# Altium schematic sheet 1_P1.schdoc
size 431 x 309 mm; Symbol: Sheet-Symbol_A3; Device: Sheet-Symbol_A3; Company: PCBCrew.com; Drawed: DumTux; Reviewed: EasyEDA Pro; Version: V0.1; Page Size: A3; @Project Name: BLDGOT ESP32 Temperature Controller; @Page Count: 2; @Update Date: 2023-02-26; @Create Date: 2023-02-25; @Schematic Name: Temperature Controller; Part Number: JLCPCB-001; @Page No: 1; @Page Name: P1
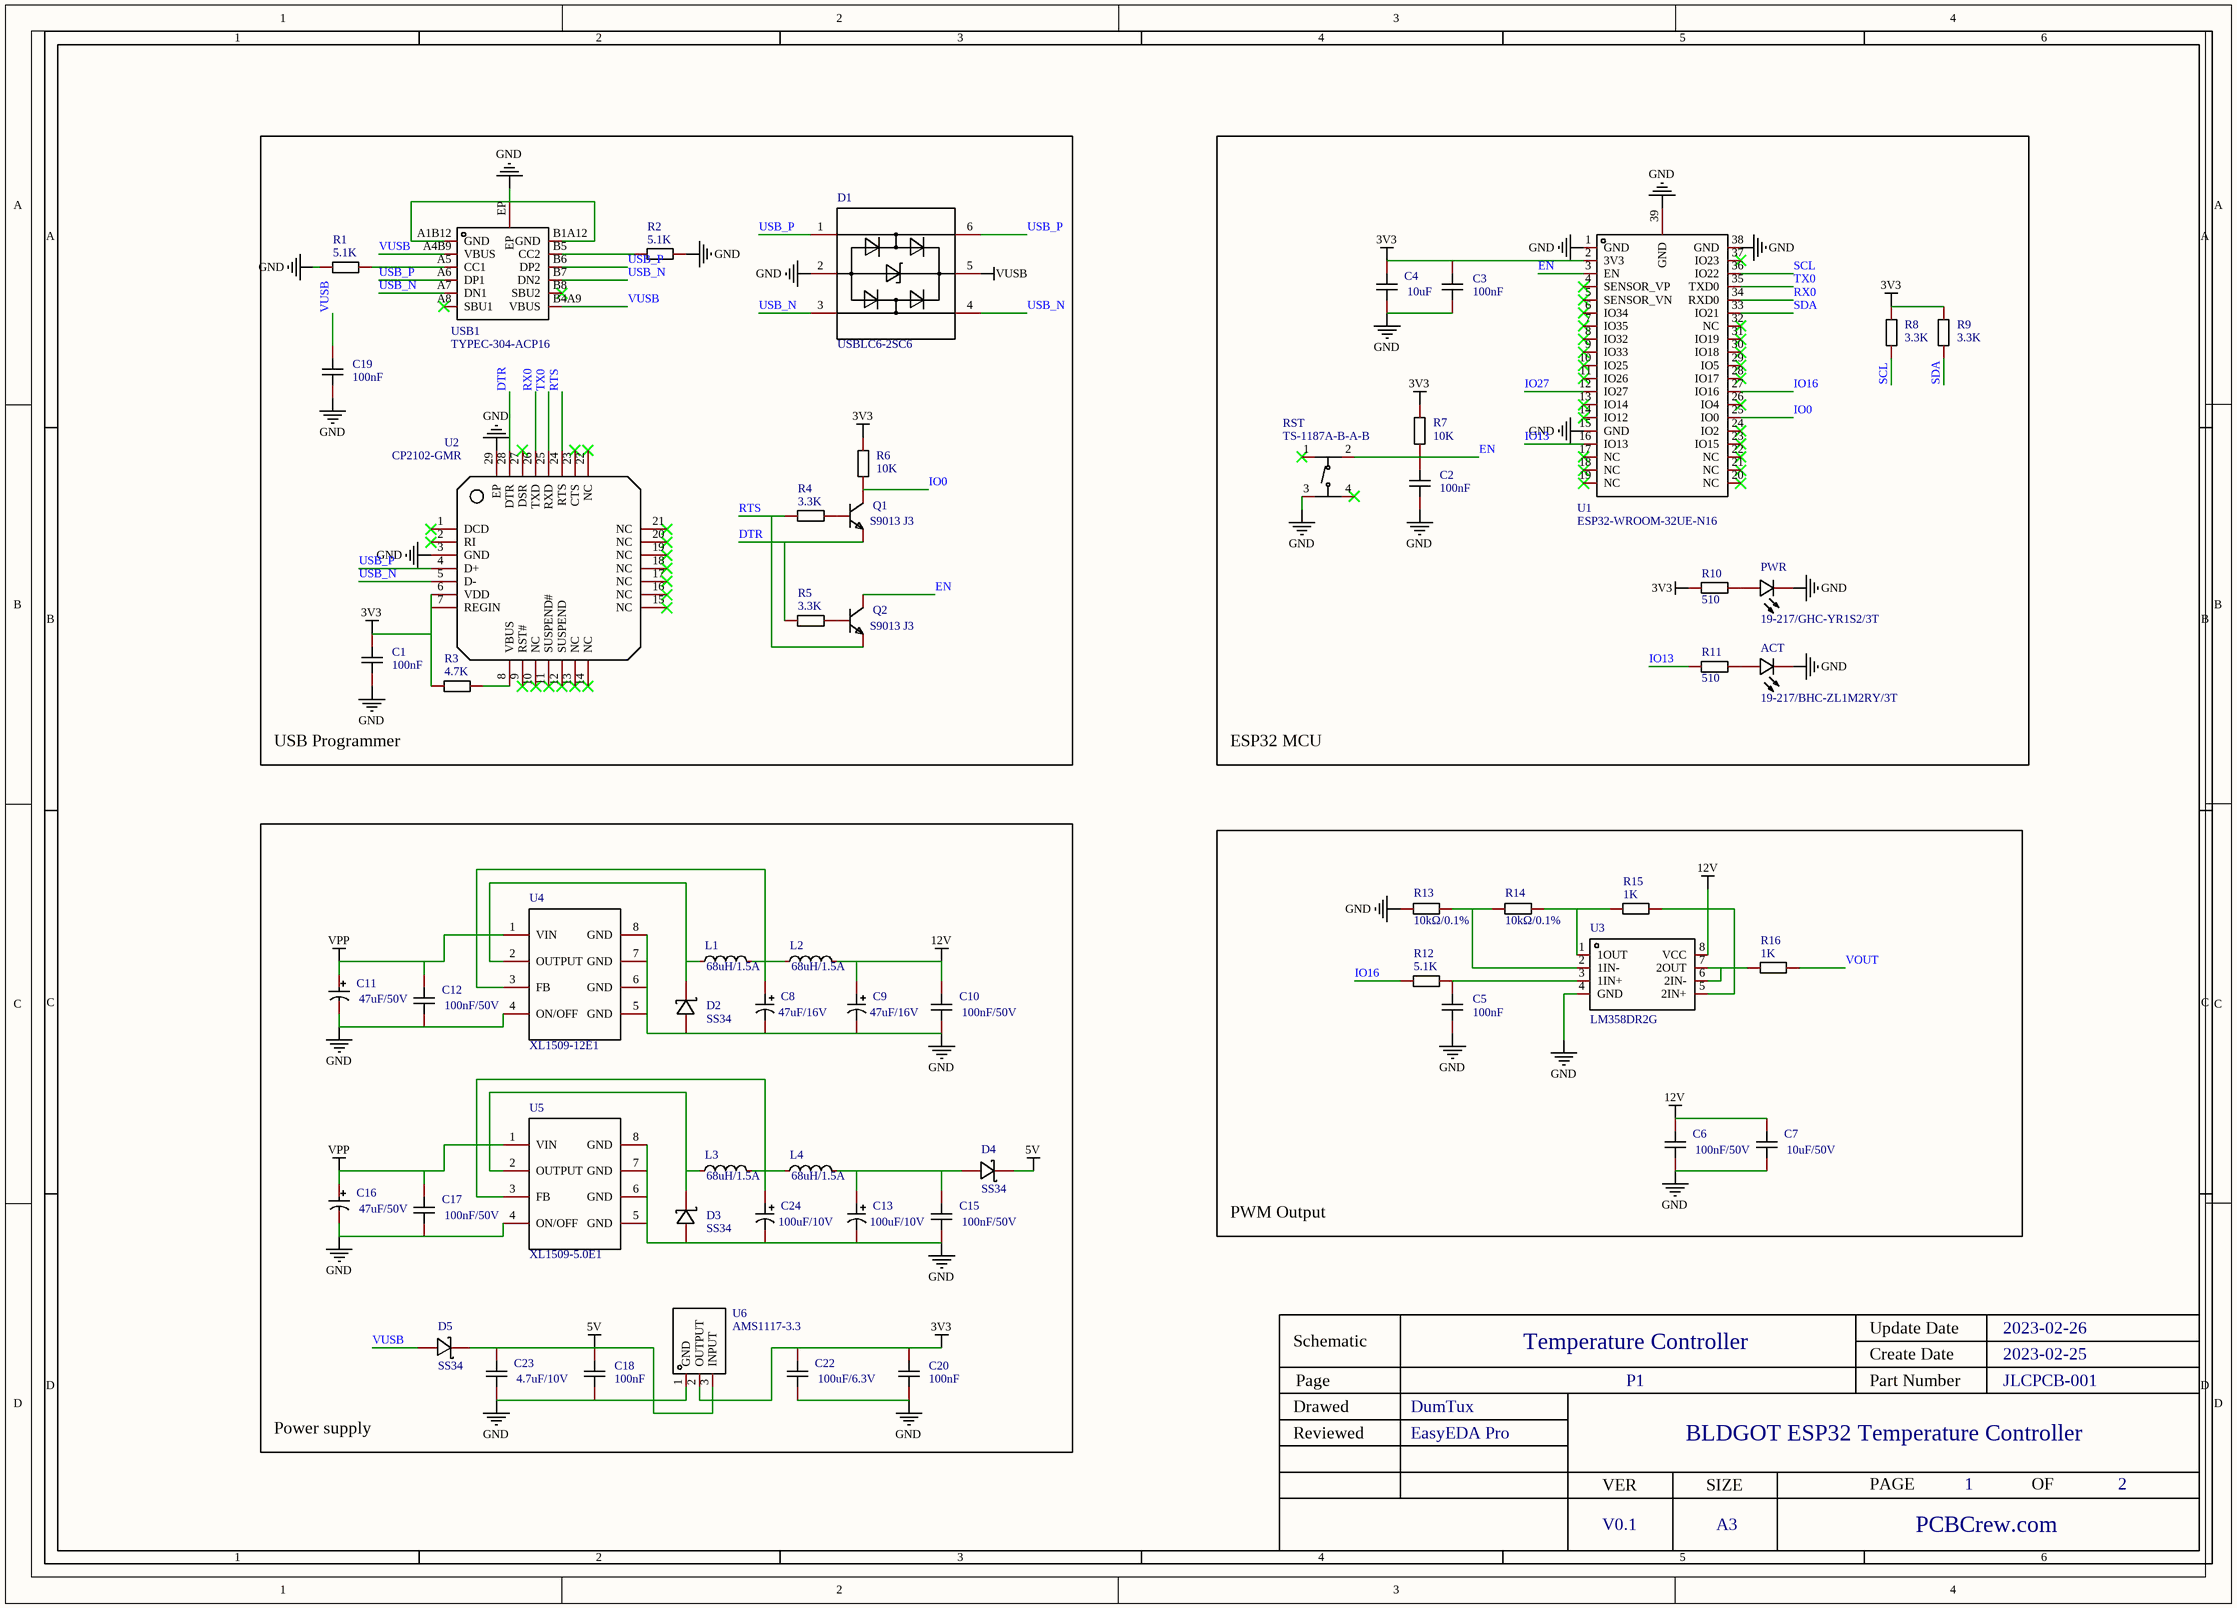
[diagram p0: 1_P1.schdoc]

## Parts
ACT  19-217/BHC-ZL1M2RY/3T  [LED0603-RD]
C1  100nF  [C0402]
C2  100nF  [C0402]
C3  100nF  [C0402]
C4  10uF  [C0603]
C5  100nF  [C0402]
C6  100nF/50V  [C0603]
C7  10uF/50V  [C0805]
C8  47uF/16V  [CAP-SMD_BD5.0-L5.3-W5.3-RD]
C9  47uF/16V  [CAP-SMD_BD5.0-L5.3-W5.3-RD]
C10  100nF/50V  [C0603]
C11  47uF/50V  [CAP-SMD_BD6.3-L6.6-W6.6-FD]
C12  100nF/50V  [C0603]
C13  100uF/10V  [CAP-SMD_BD5.0-L5.3-W5.3-RD]
C15  100nF/50V  [C0603]
C16  47uF/50V  [CAP-SMD_BD6.3-L6.6-W6.6-FD]
C17  100nF/50V  [C0603]
C18  100nF  [C0402]
C19  100nF  [C0402]
C20  100nF  [C0402]
C22  100uF/6.3V  [C1210]
C23  4.7uF/10V  [C1210]
C24  100uF/10V  [CAP-SMD_BD5.0-L5.3-W5.3-RD]
D1  USBLC6-2SC6  [SOT-23-6_L2.9-W1.6-P0.95-LS2.8-BR]
D2  SS34  [SMA_L4.3-W2.6-LS5.2-RD]
D3  SS34  [SMA_L4.3-W2.6-LS5.2-RD]
D4  SS34  [SMA_L4.3-W2.6-LS5.2-RD]
D5  SS34  [SMA_L4.3-W2.6-LS5.2-RD]
L1  68uH/1.5A  [IND-SMD_L7.1-W6.6]
L2  68uH/1.5A  [IND-SMD_L7.1-W6.6]
L3  68uH/1.5A  [IND-SMD_L7.1-W6.6]
L4  68uH/1.5A  [IND-SMD_L7.1-W6.6]
PWR  19-217/GHC-YR1S2/3T  [LED0603-RD]
Q1  S9013 J3  [SOT-23-3_L2.9-W1.3-P1.90-LS2.4-BR]
Q2  S9013 J3  [SOT-23-3_L2.9-W1.3-P1.90-LS2.4-BR]
R1  5.1K  [R0402]
R2  5.1K  [R0402]
R3  4.7K  [R0402]
R4  3.3K  [R0402]
R5  3.3K  [R0402]
R6  10K  [R0402]
R7  10K  [R0402]
R8  3.3K  [R0402]
R9  3.3K  [R0402]
R10  510  [R0402]
R11  510  [R0402]
R12  5.1K  [R0402]
R13  10kΩ/0.1%  [R0402]
R14  10kΩ/0.1%  [R0402]
R15  1K  [R0402]
R16  1K  [R0402]
RST  TS-1187A-B-A-B  [SW-SMD_4P-L5.1-W5.1-P3.70-LS6.5-TL-2]
U1  ESP32-WROOM-32UE-N16  [WIFI-SMD_ESP32-WROOM-32UE]
U2  CP2102-GMR  [WQFN-28_L5.0-W5.0-P0.50-BL-EP3.2]
U3  LM358DR2G  [SOIC-8_L5.0-W4.0-P1.27-LS6.0-BL]
U4  XL1509-12E1  [SOIC-8_L5.0-W4.0-P1.27-LS6.0-BL]
U5  XL1509-5.0E1  [SOIC-8_L5.0-W4.0-P1.27-LS6.0-BL]
U6  AMS1117-3.3  [SOT-89-3_L4.5-W2.5-P1.50-LS4.1-BL]
USB1  TYPEC-304-ACP16  [USB-C-SMD_TYPE-C-16P-1]

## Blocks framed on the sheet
USB Programmer: C1 C19 D1 Q1 Q2 R1-R6 U2 USB1
ESP32 MCU: ACT C2-C4 PWR R7-R11 RST U1
Power supply: C8-C13 C15-C18 C20 C22-C24 D2-D5 L1-L4 U4-U6
PWM Output: C5-C7 R12-R16 U3

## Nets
3V3: C1.1 C3.1 C4.2 C20.1 C22.2 R3.1 R6.2 R7.2 R8.2 R9.2 R10.2 U1.2(3V3) U2.6(VDD) U2.7(REGIN) U6.2(OUTPUT)
5V: C18.1 C23.2 D4.1(K) D5.1(K) U6.3(INPUT)
12V: C6.2 C7.2 C9.1 C10.2 L2.1 U3.8(VCC)
GND: ACT.1(C) C1.2 C2.2 C3.2 C4.1 C5.2 C6.1 C7.1 C8.2 C9.2 C10.1 C11.2 C12.1 C13.2 C15.1 C16.2 C17.1 C18.2 C19.2 C20.2 C22.1 C23.1 C24.2 D1.2 D2.2(A) D3.2(A) PWR.1(C) R1.1 R2.2 R13.1 RST.3(C) U1.1(GND) U1.15(GND) U1.38(GND) U1.39(GND) U2.3(GND) U2.29(EP) U3.4(GND) U4.4(ON/OFF) U4.5(GND) U4.6(GND) U4.7(GND) U4.8(GND) U5.4(ON/OFF) U5.5(GND) U5.6(GND) U5.7(GND) U5.8(GND) U6.1(GND) USB1.A1B12(GND) USB1.B1A12(GND) USB1.EP
VPP: C11.1 C12.2 C16.1 C17.2 U4.1(VIN) U5.1(VIN)
VUSB: C19.1 D1.5 D5.2(A) USB1.A4B9(VBUS) USB1.B4A9(VBUS)
DTR: Q1.2(E) R5.1 U2.28(DTR)
EN: C2.1 Q2.3(C) R7.1 RST.2(B) U1.3(EN)
IO0: Q1.3(C) R6.1 U1.25(IO0)
IO13: R11.2 U1.16(IO13)
IO16: R12.1 U1.27(IO16)
IO27: U1.12(IO27)
RTS: Q2.2(E) R4.1 U2.24(RTS)
RX0: U1.34(RXD0) U2.26(TXD)
SCL: R8.1 U1.36(IO22)
SDA: R9.1 U1.33(IO21)
TX0: U1.35(TXD0) U2.25(RXD)
USB_N: D1.3 D1.4 U2.5(D-) USB1.A7(DN1) USB1.B7(DN2)
USB_P: D1.1 D1.6 U2.4(D+) USB1.A6(DP1) USB1.B6(DP2)
VOUT: R16.2
NetACT_2: ACT.2(A) R11.1
NetC5_1: C5.1 R12.2 U3.3(1IN+)
NetC8_1: C8.1 L1.1 L2.2 U4.3(FB)
NetC13_1: C13.1 C15.2 D4.2(A) L4.1
NetC24_1: C24.1 L3.1 L4.2 U5.3(FB)
NetD2_1: D2.1(K) L1.2 U4.2(OUTPUT)
NetD3_1: D3.1(K) L3.2 U5.2(OUTPUT)
NetPWR_2: PWR.2(A) R10.1
NetQ1_1: Q1.1(B) R4.2
NetQ2_1: Q2.1(B) R5.2
NetR1_2: R1.2 USB1.A5(CC1)
NetR2_1: R2.1 USB1.B5(CC2)
NetR3_2: R3.2 U2.8(VBUS)
NetR13_2: R13.2 R14.1 U3.2(1IN-)
NetR14_2: R14.2 R15.1 U3.1(1OUT)
NetR15_2: R15.2 U3.5(2IN+)
NetR16_1: R16.1 U3.6(2IN-) U3.7(2OUT)

Not connected (* = marked no-connect by the designer): RST 1(A)* 4(D)*; U1 4(SENSOR_VP)* 5(SENSOR_VN)* 6(IO34)* 7(IO35)* 8(IO32)* 9(IO33)* 10(IO25)* 11(IO26)* 13(IO14)* 14(IO12)* 17(NC)* 18(NC)* 19(NC)* 20(NC)* 21(NC)* 22(NC)* 23(IO15)* 24(IO2)* 26(IO4)* 28(IO17)* 29(IO5)* 30(IO18)* 31(IO19)* 32(NC)* 37(IO23)*; U2 1(DCD)* 2(RI)* 9(RST#)* 10(NC)* 11(SUSPEND#)* 12(SUSPEND)* 13(NC)* 14(NC)* 15(NC)* 16(NC)* 17(NC)* 18(NC)* 19(NC)* 20(NC)* 21(NC)* 22(NC)* 23(CTS)* 27(DSR)*; USB1 A8(SBU1)* B8(SBU2)*

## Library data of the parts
ACT = 19-217/BHC-ZL1M2RY/3T: Mounting Type:SurfaceMount Illumination Color:Blue Luminous Intensity (IF=20mA): Dominant Wavelength / Coordinate rank:; Manufacturer: EVERLIGHT(亿光); Add into BOM: yes; Illumination Color: Blue
C1-C3 C5 C18-C20 = CAP_0402: Symbol: CAP; Convert to PCB: yes
C4 = CL10A106KP8NNNC: Capacitance: Tolerance:±10% Tolerance:±10% Voltage Rated: Temperature Coefficient:; Manufacturer: SAMSUNG(三星); Add into BOM: yes; Tolerance: ±10%
C6 C10 C12 C15 C17 = CC0603KRX7R9BB104: Capacitance: Tolerance:±10% Tolerance:±10% Voltage Rated: Temperature Coefficient:; Manufacturer: YAGEO(国巨); Add into BOM: yes; Tolerance: ±10%
C7 = GRM21BR61H106KE43L: Capacitance: Tolerance:±10% Tolerance:±10% Voltage Rated: Temperature Coefficient:; Manufacturer: muRata(村田); Add into BOM: yes; Tolerance: ±10%
C8 C9 = CK1C470M-CRD54: Capacitance: Tolerance:±20% Tolerance:±20% Rated Voltage: φD: L: Ripple Current:31mA@120Hz Lifetime @ Temp:2000hrs@105℃ Operating Temperature:-55℃~+105℃ Operating Temperature:-55℃~+105℃; Manufacturer: ROQANG(容强); Symbol: CK1C470M-CRD54_C3001232; Add into BOM: yes; Tolerance: ±20%
C11 C16 = CS1H470M-CRE77　: Capacitance: Tolerance:±20% Tolerance:±20% Rated Voltage: φD: L: Ripple Current:- Equivalent Series Resistance(ESR):- Lifetime @ Temp:2000hrs@105℃ Operating Temperature:-40℃~+105℃ Operating Temperature:-40℃~+105℃; Manufacturer: ST(先科); Add into BOM: yes; Tolerance: ±20%
C13 C24 = CS1A101M-CRD54: Capacitance: Tolerance:±20% Tolerance:±20% Rated Voltage: φD: L: Ripple Current:49mA@120Hz Lifetime @ Temp:1000hrs@105℃ Operating Temperature:-40℃~+105℃ Operating Temperature:-40℃~+105℃; Manufacturer: ROQANG(容强); Symbol: CS1A101M-CRD54_C3001205; Add into BOM: yes; Tolerance: ±20%
C22 = JMK325BJ107MM-T: Capacitance: Tolerance:±20% Tolerance:±20% Voltage Rated: Temperature Coefficient:; Manufacturer: TAIYO YUDEN(太诱); Add into BOM: yes; Tolerance: ±20%
C23 = HMK325C7475KMHPE: Capacitance: Tolerance: Tolerance: Voltage Rated: Temperature Coefficient:; Manufacturer: TAIYO YUDEN(太诱); Add into BOM: yes
D1 = USBLC6-2SC6_C7519: Polarity:Unidirectional Reverse Stand-Off Voltage (Vrwm):5.25V Breakdown Voltage (VBR):6V Peak Pulse Current(Ipp)@8/20us:5A Clamping Voltage@Ipp:17V Peak Pulse Power(Ppp)@8/20us:- Junction Capacitance(Cj)@1MHz:- Operating Temperature:-40℃~+125℃@(Tj) Opera; Manufacturer: ST(意法半导体); Add into BOM: yes; Reverse Stand-Off Voltage (Vrwm): 5.25V; Breakdown Voltage (VBR): 6V; Peak Pulse Current(Ipp)@8/20us: 5A; Clamping Voltage@Ipp: 17V
D2-D5 = SS34_C8678: Diode Configuration:Single Reverse Voltage (Vr):40V Average Rectified Current (Io):3A Forward Voltage (Vf@If):0.55V@3A Reverse Leakage Current (Ir):0.5mA@40V; Manufacturer: MDD; Add into BOM: yes; Diode Configuration: Single; Reverse Voltage (Vr): 40V; Average Rectified Current (Io): 3A
L1-L4 = SMMS0650-680M: Inductance: Tolerance: Tolerance: Rated Current: Saturation Current (Isat):2A DC Resistance (DCR): Ratings:- Lead Spacing:- φD:- Length:- Width:- Height:-; Manufacturer: SXN(顺翔诺); Add into BOM: yes; Saturation Current (Isat): 2A
PWR = 19-217/GHC-YR1S2/3T: Emitted Color:Emerald Diode Configuration:- Lens Color:Colorless transparence Dominant Wavelength:520nm~535nm Dominant Wavelength:520nm~535nm Peak Wavelength:518nm Color Temperature:- Color Temperature:- Forward Current:20mA Power Dissipation:110mW Viewin; Manufacturer: EVERLIGHT(亿光); Add into BOM: yes; Peak Wavelength: 518nm; Forward Current: 20mA; Power Dissipation: 110mW; Viewing Angle: 120°
Q1 Q2 = S9013 J3_C6749: Transistor Type: Collector-Emitter Breakdown Voltage (Vceo): Collector Current (Ic): Power Dissipation (Pd): Collector Cut-Off Current (Icbo):100nA Collector-Emitter Saturation Voltage (VCE(sat)@Ic,Ib):600mV@500mA,50mA DC Current Gain (hFE@Ic,Vce):200@50m; Manufacturer: CJ(江苏长电/长晶); Add into BOM: yes; Collector Cut-Off Current (Icbo): 100nA; DC Current Gain (hFE@Ic,Vce): 200@50mA,1V; Transition Frequency (fT): 150MHz; NAME: E; NUMBER: 2
R1-R12 R15 R16 = Res_0402: Symbol: Res; Convert to PCB: yes
R13 R14 = AR02BTC1002: Type:Thin Film Resistor Resistance: Tolerance:±0.1% Tolerance:±0.1% Power(Watts): Temperature Coefficient:±25ppm/℃ Temperature Coefficient:±25ppm/℃ Overload Voltage (Max): Operating Temperature Range:-55℃~+155℃ Operating Temperature Range:-55℃~+155℃; Manufacturer: Viking(光颉); Add into BOM: yes; Tolerance: ±0.1%
RST = TS-1187A-B-A-B: Contact Current:50mA Voltage Rating (DC):12V Insulation Resistance:- Circuit:SPST Mounting Style:Brick nogging Actuator Style:Round Button Actuator/Cap Color:金色 With Lamp:No Operating Force:160gf Mechanical Life:100000 Operating Temperature:-30℃~+85℃ Oper; Manufacturer: XKB Connectivity(中国星坤); Add into BOM: yes; Contact Current: 50mA; Voltage Rating (DC): 12V; Circuit: SPST; Actuator/Cap Color: 金色; With Lamp: No; Operating Force: 160gf; Mechanical Life: 100000; Switch Length: 5.1mm; Switch Height: 1.5mm
U1 = ESP32-WROOM-32UE-N16_C701346: Manufacturer: ESPRESSIF(乐鑫); Symbol: ESP32-WROOM-32UE(16MB); Add into BOM: yes
U2 = CP2102-GMR: Type: Protocol: Number of Drivers/Receivers: Data Rate: Supply Voltage:; Manufacturer: SILICON LABS(芯科); Add into BOM: yes
U3 = LM358DR2G: Amplifier Type:General Purpose Number of Circuits: Gain Bandwidth Product（GBP）: Slew Rate（SR）: Output Type: Supply Voltage（Single）: Iq per channel (Typ): Operating Temperature:; Manufacturer: onsemi(安森美); Add into BOM: yes
U4 = XL1509-12E1: Function:Step-down type Synchronous Rectification:- Number of Outputs:- Topology:- Input Voltage:- Input Voltage:- Output Current (Max):- Switching Frequency:-; Manufacturer: XLSEMI(芯龙); Add into BOM: yes
U5 = XL1509-5.0E1: Function:Step-down type Synchronous Rectification:- Number of Outputs:- Topology:- Input Voltage:- Input Voltage:- Output Current (Max):- Switching Frequency:-; Manufacturer: XLSEMI(芯龙); Add into BOM: yes
U6 = AMS1117-3.3_C2904742: Output Type: Output Polarity:Positive Number of Outputs:1 Maximum Input Voltage:20V Output Voltage:3.3V~3.3V Output Voltage:3.3V~3.3V Dropout Voltage:1.25V@(1A) Output Current:1A Power Supply Rejection Ratio (PSRR):75dB@(120Hz) Operating Temperature:±125℃; Manufacturer: YONGYUTAI(永裕泰); Add into BOM: yes; Number of Outputs: 1; Maximum Input Voltage: 20V
USB1 = TYPEC-304-ACP16: Connector Type:Type-C Standard:- Gender:Female Number of Contacts:16 Number of Ports:1 Mounting Style:Surface Mount Current Rating - Power (Max):3A Contact Material:Copper Contact Plating:Gold plating Operating Temperature Range:-40℃~+85℃ Operating Temper; Manufacturer: XUNPU(讯普); Add into BOM: yes; Connector Type: Type-C; Gender: Female; Number of Contacts: 16; Number of Ports: 1; Current Rating - Power (Max): 3A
